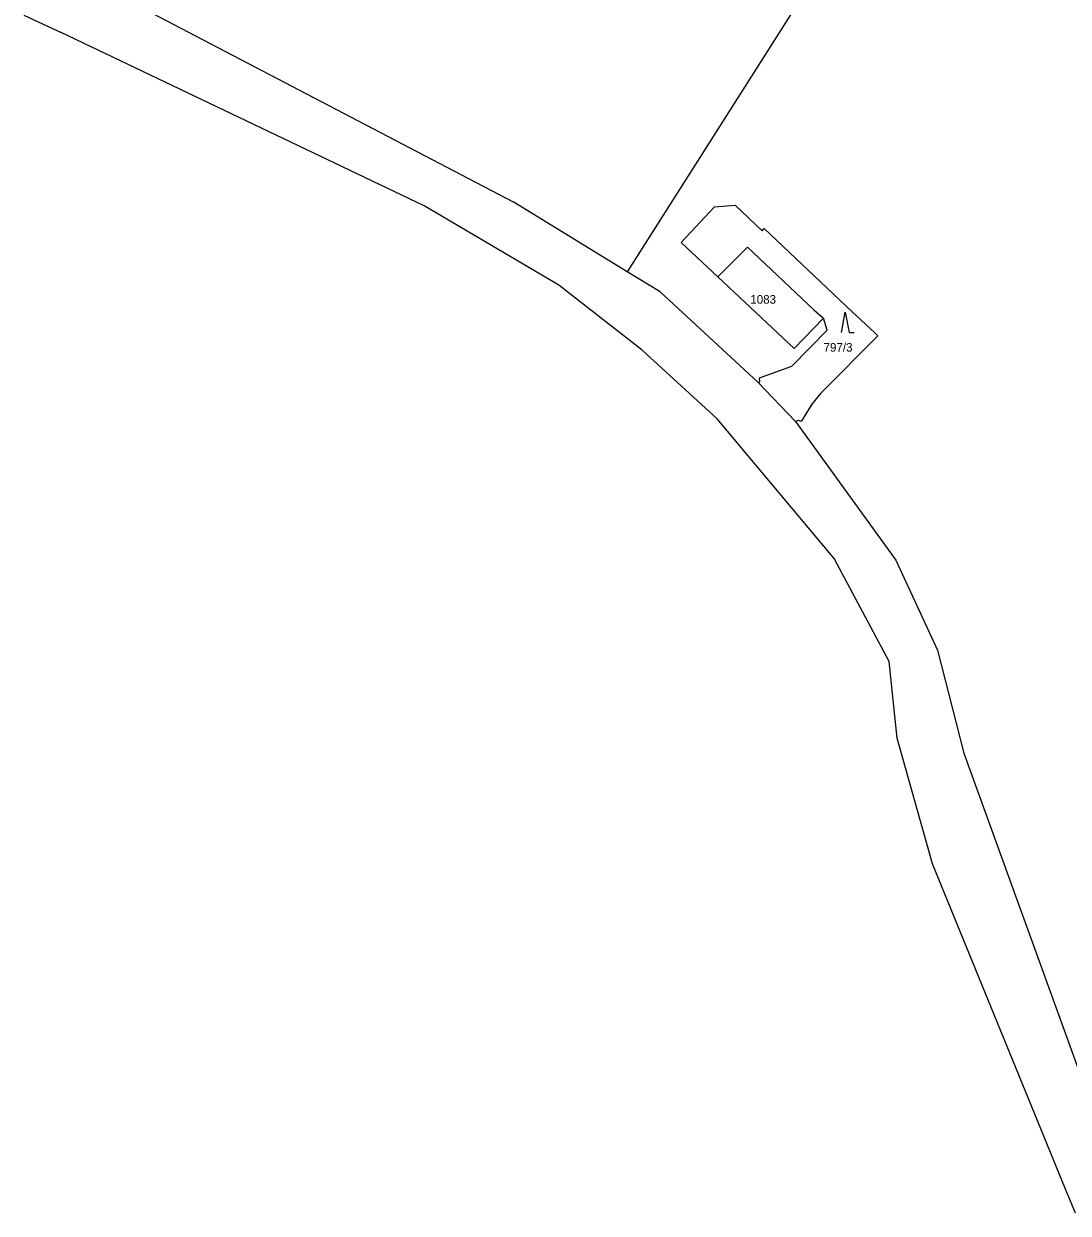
# Model space of a CAD drawing. Extents: x -801907 to -800293, y -1016964 to -1015684.
# Drawn here: x -801511.3 to -801306.6, y -1016238.8 to -1016005.6 of the extents above; entities that cross this region are included whole.
import ezdxf

# ---------------------------------------------------------------- set-up
doc = ezdxf.new("R2010")
doc.units = 0
for name, color, linetype in [('Default', 7, 'Continuous'), ('KN_HRANICE', 7, 'Continuous'), ('KN_KULTURY', 7, 'Continuous'), ('KN_PARCELY', 7, 'Continuous')]:
    doc.layers.add(name, color=color, linetype=linetype)

# ---------------------------------------------------------------- blocks, each defined once
blk = doc.blocks.new('308')
at = {"layer": 'Default'}
blk.add_lwpolyline([(-0.75, 0), (0, 4), (0.75, 0), (1.75, 0)], dxfattribs=at)

msp = doc.modelspace()

# ---------------------------------------------------------------- linework, layer by layer
at = {"layer": 'KN_HRANICE'}
for p, q in [((-801345.03, -1015978.6), (-801393.03, -1016054.26)), ((-801508.87, -1015991.61), (-801415.39, -1016040.55)), ((-801511.29, -1016003.9), (-801503.99, -1016007.34)), ((-801432.84, -1016041.32), (-801503.99, -1016007.34)), ((-801393.03, -1016054.26), (-801415.39, -1016040.55)), ((-801406.47, -1016056.88), (-801432.84, -1016041.32)), ((-801382.44, -1016048.48), (-801375.92, -1016041.5)), ((-801375.92, -1016041.5), (-801371.92, -1016041.18)), ((-801371.92, -1016041.18), (-801366.61, -1016046.22)), ((-801366.61, -1016046.22), (-801366.2, -1016045.78)), ((-801366.2, -1016045.78), (-801348.98, -1016062.12)), ((-801375.26, -1016055.21), (-801382.44, -1016048.48)), ((-801375.26, -1016055.21), (-801369.46, -1016049.39)), ((-801369.46, -1016049.39), (-801356.49, -1016061.73)), ((-801386.61, -1016058.19), (-801393.03, -1016054.26)), ((-801390.13, -1016069.64), (-801406.47, -1016056.88)), ((-801360.36, -1016069.3), (-801375.26, -1016055.21)), ((-801367.43, -1016075.9), (-801386.61, -1016058.19)), ((-801356.49, -1016061.73), (-801354.58, -1016063.35)), ((-801354.58, -1016063.35), (-801360.36, -1016069.3)), ((-801353.84, -1016065.68), (-801354.58, -1016063.35)), ((-801348.98, -1016062.12), (-801344.53, -1016066.21)), ((-801360.8, -1016072.76), (-801353.84, -1016065.68)), ((-801344.53, -1016066.21), (-801343.9, -1016066.79)), ((-801343.9, -1016066.79), (-801355.08, -1016078.06)), ((-801375.43, -1016083.09), (-801390.13, -1016069.64)), ((-801367.15, -1016075.06), (-801360.8, -1016072.76)), ((-801367.06, -1016075.86), (-801367.15, -1016075.06)), ((-801367.43, -1016075.9), (-801367.06, -1016075.86)), ((-801360.06, -1016083.6), (-801367.43, -1016075.9)), ((-801355.08, -1016078.06), (-801356.87, -1016080.2)), ((-801356.87, -1016080.2), (-801358.95, -1016083.62)), ((-801352.5, -1016110.48), (-801375.43, -1016083.09)), ((-801359.51, -1016083.41), (-801360.06, -1016083.6)), ((-801360.06, -1016083.6), (-801340.38, -1016110.8)), ((-801358.95, -1016083.62), (-801359.51, -1016083.41)), ((-801341.74, -1016130.67), (-801352.5, -1016110.48)), ((-801340.38, -1016110.8), (-801332.22, -1016128.43)), ((-801332.22, -1016128.43), (-801327.07, -1016148.63)), ((-801340.16, -1016145.67), (-801341.74, -1016130.67)), ((-801333.2, -1016170.31), (-801340.16, -1016145.67)), ((-801327.07, -1016148.63), (-801296.08, -1016234.39)), ((-801307.14, -1016234.16), (-801333.2, -1016170.31)), ((-801305.22, -1016238.85), (-801307.14, -1016234.16))]:
    msp.add_line(p, q, dxfattribs=at)

# ---------------------------------------------------------------- block references
at = {"layer": 'KN_KULTURY'}
msp.add_blockref('308', (-801350.32, -1016066.15), dxfattribs=at)

# ---------------------------------------------------------------- texts
at = {"layer": 'KN_PARCELY'}
for s, p in [('1083', (-801368.93, -1016060.51)), ('797/3', (-801354.58, -1016069.91))]:
    msp.add_text(s, height=1.7, dxfattribs=at).set_placement(p)

doc.saveas('drawing.dxf')
